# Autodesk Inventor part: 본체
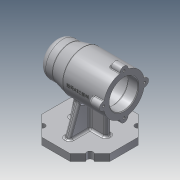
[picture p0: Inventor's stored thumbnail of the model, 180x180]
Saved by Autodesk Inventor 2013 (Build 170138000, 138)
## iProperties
Created: 2021-01
Part Number: 본체
Material: 알루미늄 6061
Document SubType Name: Modeling
Designer: 19
Density: 2.71 g/cm^3
Mass: 632.297 g
Surface Area: 613.777 cm^2
Volume: 233.32 cm^3
Author: 19
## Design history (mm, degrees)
sketch "스케치1"
  geometry: L1 (-50, 0)-(50, 0); L2 (-50, 0)-(-50, 15); L3 (-40, 25)-(-30, 25); L4 (-30, 25)-(-10, 30); L5 (-10, 30)-(50, 30); L6 (50, 30)-(50, 22); L7 (49, 21)-(35, 21); L8 (35, 21)-(35, 21); L9 (32, 24)-(-4, 24); L10 (-7, 21)-(-7, 21); L11 (-7, 21)-(-18.7, 21); L12 (-19, 20.7)-(-19, 17.5); L13 (-19, 17.5)-(-36.7, 17.5); L14 (-37, 17.2)-(-37, 16); L15 (-37, 16)-(-40.7, 16); L16 (-41, 15.7)-(-41, 10.5); L17 (-41, 10.5)-(-41, 10.5); L18 (-44, 7.5)-(-44, 0); L19 (49, 21)-(50, 22); A1 r 3 centre (-41, 7.5) between (-41, 10.5) and (-44, 7.5); A2 r 3 centre (-4, 21) between (-4, 24) and (-7, 21); A3 r 3 centre (32, 21) between (35, 21) and (32, 24); A4 r 0.3 centre (-40.7, 15.7) between (-40.7, 16) and (-41, 15.7); A5 r 0.3 centre (-36.7, 17.2) between (-36.7, 17.5) and (-37, 17.2); A6 r 0.3 centre (-18.7, 20.7) between (-18.7, 21) and (-19, 20.7); A7 r 10 centre (-40, 15) between (-40, 25) and (-50, 15); 11 further points
  constraints: 38 end point, 20 point on line, 14 point on circle, 14 tangent, 9 parallel, 7 centre point, 6 perpendicular, 4 equal radius, 1 coincident, 1 collinear, 1 horizontal, 1 midpoint
  dimensions: "d0" = 100 distance of L1.start L1.end; "d1" = 60 diameter of L5 L1; "d2" = 50 diameter of L3 L1; "d3" = 20 distance of point (-50, 25) L3.end; "d4" = 40 distance from line of L2 L4.end; "d5" = 42 diameter of L7 L1; "d6" = 48 diameter of L9 L1; "d7" = 42 diameter of L11 L1 (= d5); "d8" = 35 diameter of L13 L1; "d9" = 32 diameter of L15 L1; "d10" = 21 diameter of L17 L1; "d11" = 15 distance of point (50, 21) L7.end; "d12" = 42 distance of point (35, 24) point (-7, 24); "d13" = 12 distance of L10.end point (-19, 21); "d14" = 18 distance of L12.end point (-37, 17.5); "d15" = 4 distance of L14.end point (-41, 16); "d16" = 3 distance of L16.end point (-44, 10.5); "d17" = 3 radius of A1; "d18" = 0.3 radius of A4; "d19" = 1 distance of L7.start point (50, 21); "d20" = 1 distance of L6.end point (50, 21) (= d19); "d21" = 10 radius of A7
revolve "회전1" sketch "스케치1" stored, may be unused: angle "d22" = 90 deg
node "작업 평면1"
sketch "스케치2"
  geometry: L1 (-50, 20.711)-(-20.711, 50); L2 (-20.711, 50)-(20.711, 50); L3 (20.711, 50)-(50, 20.711); L4 (50, 20.711)-(50, -20.711); L5 (50, -20.711)-(20.711, -50); L6 (20.711, -50)-(-20.711, -50); L7 (-20.711, -50)-(-50, -20.711); L8 (-50, -20.711)-(-50, 20.711); L9 (-50, 30)-(-50, -30) reference; L10 (-35.355, -35.355)-(35.355, 35.355); L11 (-35.355, 35.355)-(35.355, -35.355); A1 r 50 centre (0, 0) between (-35.355, 35.355) and (-35.355, -35.355); A2 r 4.5 centre (35.355, -35.355) between (38.537, -32.173) and (32.173, -38.537); A3 r 4.5 centre (-35.355, 35.355) between (-38.537, 32.173) and (-32.173, 38.537); A4 r 4.5 centre (35.355, 35.355) between (32.173, 38.537) and (38.537, 32.173); A5 r 4.5 centre (-35.355, -35.355) between (-32.173, -38.537) and (-38.537, -32.173); A6 r 4.5 centre (35.355, -35.355) between (32.173, -38.537) and (38.537, -32.173); A7 r 4.5 centre (-35.355, -35.355) between (-38.537, -32.173) and (-32.173, -38.537); A8 r 4.5 centre (-35.355, 35.355) between (-32.173, 38.537) and (-38.537, 32.173); A9 r 4.5 centre (35.355, 35.355) between (38.537, 32.173) and (32.173, 38.537); 2 further points
  constraints: 20 end point, 19 point on circle, 9 centre point, 8 point on line, 5 midpoint, 2 coincident, 1 collinear, 17 other
  dimensions: "d24" = 100 diameter of A1; "d25" = 50 distance from line of point (0, 0) L6; "d26" = 9 diameter of A2; "d27" = 9 diameter of A3; "d28" = 9 diameter of A4; "d29" = 9 diameter of A5
extrude "돌출1" join sketch "스케치2" distance "d30" = 10; taper "d31" = 0 deg
sketch "스케치5"
  geometry: L1 (50, -20.711)-(50, 20.711) reference; L2 (-50, 20.711)-(-50, -20.711) reference; L3 (-27, -4)-(27, -4); L4 (27, -4)-(27, 4); L5 (27, 4)-(-27, 4); L6 (-27, 4)-(-27, -4); 1 further point
  constraints: 8 end point, 2 parallel, 1 horizontal, 1 perpendicular
  dimensions: "d37" = 8 distance of L3.end L4.end; "d39" = 23 distance between parallel lines of L1 L4; "d40" = 23 distance between parallel lines of L2 L6; "d41" = 4 distance from line of L5 point (0, 0)
extrude "돌출3" join sketch "스케치5" stored distance "d42" = 8; taper "d43" = 0 deg
feature "면 기울기1" dims angle "d44" = 11 deg
sketch "스케치6"
  geometry: L1 (-65, -50)-(-75, -50) reference; L2 (-75, -50)-(-75, 50) reference; L3 (-75, 50)-(-65, 50) reference; L4 (-65, 50)-(-65, 4) reference; L5 (-65, 4)-(-29.732, 4) reference; L6 (-29.732, -4)-(-65, -4) reference; L7 (-65, -4)-(-65, -50) reference; L8 (-65, 35)-(-22.707, 19.606); L9 (-22.707, -19.606)-(-65, -35); C1 r 24 at (0, 0) reference; A1 r 30 centre (0, 0) between (-29.732, -4) and (-29.732, 4) reference; 1 further point
  constraints: 4 end point, 2 point on circle, 2 point on line
  dimensions: "d45" = 15 distance from line of L9.end L1; "d46" = 15 distance from line of L3 L8.start; "d47" = 110 deg angle of L7 L9; "d48" = 110 deg angle of L4 L8
extrude "돌출4" join sketch "스케치6" stored distance "d49" = 8; taper "d50" = 0 deg
sketch "스케치7"
  geometry: C1 r 22 at (0, 0) reference; C2 r 6 at (0, 30); 1 further point
  constraints: 2 vertical alignment, 1 centre point, 1 other
  dimensions: "d51" = 12 diameter of C2
extrude "돌출5" join sketch "스케치7" distance "d52" = 16; taper "d53" = 0 deg
sketch "스케치8"
  geometry: A1 r 6 centre (0, 0) between (5.97, -0.6) and (-5.97, -0.6) reference; 1 further point
  constraints: 1 coincident
hole "구멍1" sketch "스케치8" at (0, 0) diameter "d54" = 3.242; stored, may be unused: countersink angle "d58" = 90 deg, drill point angle "d60" = 118 deg; dims "d55" = 8, "d56" = 4, "d57" = 2, "d59" = 10
fillet "모깎기1" dims "d61" = 3
fillet "모깎기2" dims "d65" = 3
fillet "모깎기3" dims "d66" = 3
fillet "모깎기4" dims "d67" = 1
fillet "모깎기5" dims "d68" = 3
node "작업 평면2"
sketch "스케치9"
  geometry: L1 (50, 6.771)-(50, 29.226) reference; 2 further points
  constraints: 1 horizontal alignment, 1 other
  dimensions: "d70" = 38 distance from line of point (12, 0) L1
feature "엠보싱1" sketch "스케치9" dims "d71" = 0.5, "d72" = 0
node "솔리드1"
pattern_circular "원형 패턴1" dims "d63" = 360 deg
node "절단 모서리 투영3"
other parameters: "d23" = -75, "d69" = 71
